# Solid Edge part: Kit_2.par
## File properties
Author: bmolnar
Last saved by: bmolnar
Revision: 76
Sűrűség: 0,000 kg/m^3
Pontosság: 0,990
Username: bmolnar
Dokumentum tartalom típus: 0
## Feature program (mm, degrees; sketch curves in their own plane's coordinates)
base feature "unnamed BaseFeature 1"
sketch for "Furat_1" plane through (-18.15, -81.65, 0) normal (1, 0, 0) x-axis (0, 0, -1)
  hole centre (0, 13.85) bore radius 2.067
hole "Furat_1" nominal diameter 5 finite  ThreadDepth = 5 mm; StartChamferOffset = 0.6 mm; StartChamferAngle = 45 deg
sketch for "Furat_2" plane through (-11, -70.2, -11) normal (0, -1, 0) x-axis (0, 0, 1)
  hole centre (0, 0) bore radius 2.067
hole "Furat_2" nominal diameter 5
sketch for "unnamed Hole 1" plane through (-11, -70.2, -11) normal (0, -1, 0) x-axis (0, 0, 1)
  hole centre (22, 0) bore radius 2.067
hole "unnamed Hole 1"
sketch for "unnamed Hole 2" plane through (-11, -70.2, -11) normal (0, -1, 0) x-axis (0, 0, 1)
  hole centre (22, -22) bore radius 2.067
hole "unnamed Hole 2"
sketch for "unnamed Hole 3" plane through (-11, -70.2, -11) normal (0, -1, 0) x-axis (0, 0, 1)
  hole centre (0, -22) bore radius 2.067
hole "unnamed Hole 3"
pattern "unnamed Pattern 1" of "Furat_2", "unnamed Hole 1", "unnamed Hole 2", "unnamed Hole 3"
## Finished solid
Body 1: solid body, 258 faces, 616 edges, 372 vertices, 2 internal voids.
  Faces by surface: plane 124, cylinder 58, swept 43, cone 26, torus 7
  Edges by curve: line 361, circle 155, spline 90, curve on surface 5, intersection 4, ellipse 1
Bounding box of the edges (mm; curved faces can reach further): 36.300 x 11.800 x 36.300, from (-18.15, -75.3, -18.15) to (18.15, -63.5, 18.15).
Cylindrical faces by radius (mm): R0.2 x18, R0.4307 x1, R0.4865 x1, R2.067 x5, R3.75 x2, R4 x4, R4.1 x12, R5.24 x1, R5.45 x2, R5.55 x2, R5.7 x1, R6 x1, R6.92 x1, R7 x1, R11.25 x6
Conical faces (half-angle, radius in mm at the cone's reference point): 0.5 deg R4.5 x4, 3 deg R6.96 x1, 7 deg R6.4156 x1, 14 deg R5.12 x1, 14 deg R5.3801 x1, 17 deg R5.12 x1, 23 deg R5.7369 x1, 42.5 deg R5.1096 x1, 45 deg R2.317 x2, 45 deg R2.367 x2, 45 deg R2.667 x1, 45 deg R4.25 x2, 45 deg R5.3 x2, 45 deg R5.35 x2, 45 deg R5.85 x1, 84 deg R5.4096 x1, 85 deg R6.73 x1, 87 deg R5.1371 x1
Toroidal faces (ring radius, tube radius in mm): R3.8 r0.2 x2, R4.4 r0.4 x2, R5.6606 r0.18 x1, R6.1131 r0.26 x1, R6.72 r0.2 x1
Planar faces by outward normal: +x 5, +y 4, +z 15, -x 7, -y 16, -z 13, oblique 64
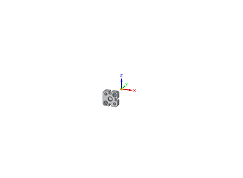
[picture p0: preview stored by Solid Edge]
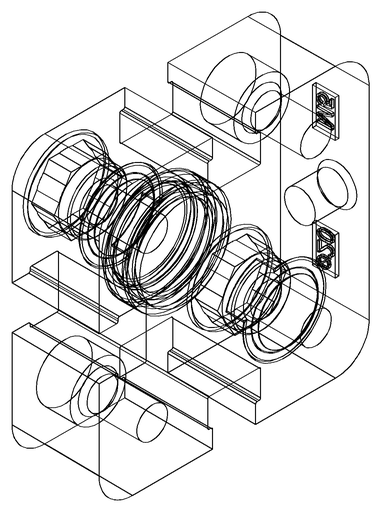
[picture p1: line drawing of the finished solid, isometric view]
